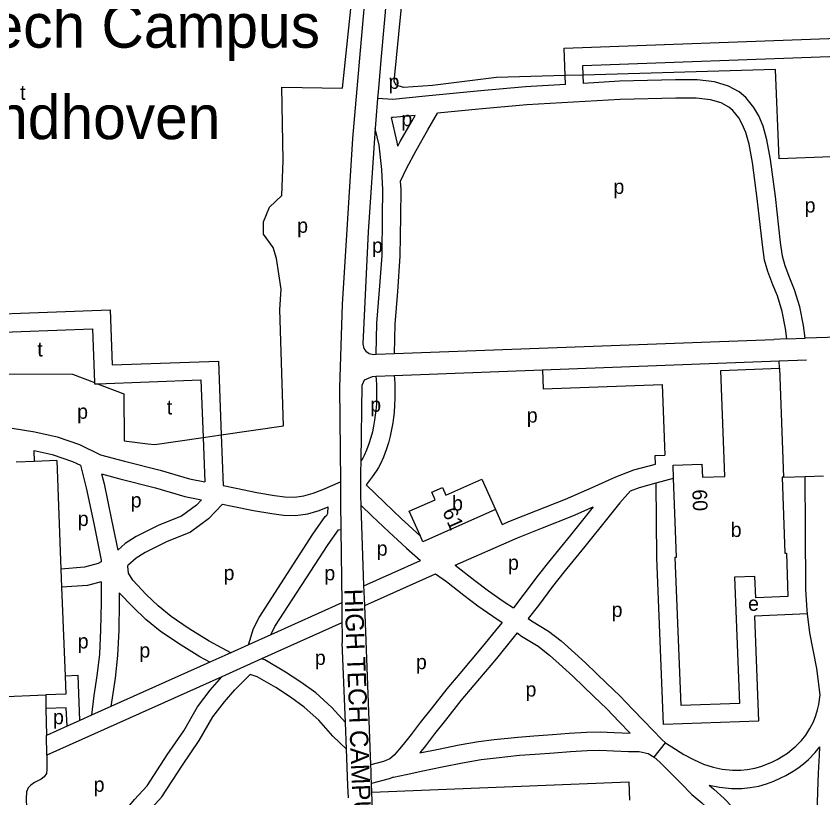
# Model space of a CAD drawing. Extents: x 158358 to 160383, y 379531 to 380764.
# Drawn here: x 159907.3 to 160127.9, y 379892.6 to 380106.3 of the extents above; entities that cross this region are included whole.
import ezdxf

# ---------------------------------------------------------------- set-up
doc = ezdxf.new("R2010")
doc.units = 0
for name, color, linetype in [('BLT_Basislijn', 7, 'Continuous'), ('BLT_Bebouwing', 7, 'Continuous'), ('BLT_Centroide', 7, 'Continuous'), ('BLT_Huisnummer', 7, 'Continuous'), ('BLT_Sport_parknaam', 7, 'Continuous'), ('BLT_Straatnaam', 7, 'Continuous'), ('BLT_Vlakafsluiter', 7, 'Continuous')]:
    doc.layers.add(name, color=color, linetype=linetype)

msp = doc.modelspace()

# ---------------------------------------------------------------- linework, layer by layer
at = {"layer": 'BLT_Basislijn'}
for p, q in [((160117.98, 380018.06), (160122.99, 380018.24)), ((160010.74, 380014.06), (160114.5, 380017.94)), ((160004.98, 380013.84), (160005.73, 380013.87)), ((160005.73, 380013.87), (160010.74, 380014.06)), ((160115.99, 380010.04), (160115.91, 380012.07)), ((160001.63, 379984.81), (160001.95, 380005.4)), ((159912.29, 379984.6), (159912.23, 379987.55)), ((160001.58, 379981.41), (160001.63, 379984.81)), ((160001.56, 379975.23), (160001.58, 379981.41)), ((160082.26, 379978.71), (160087.04, 379979.98)), ((160117.07, 379980.25), (160123.03, 379980.48)), ((160123.03, 379980.48), (160128.03, 379980.66)), ((160001.65, 379972.5), (160001.56, 379975.23)), ((160002.39, 379950.6), (160001.65, 379972.5)), ((160002.44, 379948.93), (160002.39, 379950.6)), ((160002.51, 379947.06), (160002.44, 379948.93)), ((160002.59, 379945.22), (160002.51, 379947.06)), ((160004.28, 379901.62), (160002.59, 379945.22)), ((159996.42, 379937.33), (159996.48, 379934.97)), ((159997.31, 379913.16), (159996.48, 379934.97)), ((159915.37, 379920.71), (159915.45, 379917)), ((159915.45, 379917), (159915.61, 379909.66)), ((159997.59, 379905.87), (159997.31, 379913.16)), ((159997.97, 379895.96), (159997.59, 379905.87)), ((160004.34, 379899.95), (160004.28, 379901.62)), ((160004.41, 379898.31), (160004.34, 379899.95))]:
    msp.add_line(p, q, dxfattribs=at)
for points in [[(160010.67, 380088.45), (160019.2, 380175.38)], [(160009.06, 380172.98), (160004.59, 380131.94), (160003.46, 380120.81), (160001.19, 380094.85)], [(160015.33, 380174.69), (160010.57, 380131.9), (160008.55, 380111.65), (160007.13, 380095.3)], [(159996.53, 380086.65), (160005.42, 380171.89)], [(160057.38, 380090.08), (160057.1, 380097.61), (160131.93, 380100.35)], [(160001.19, 380094.85), (159999.24, 380072.88)], [(160007.13, 380095.3), (160006.38, 380086.62)], [(160062.37, 380090.22), (160062.28, 380092.8), (160132.13, 380095.36), (160133.74, 380051.16), (160150.07, 380051.76), (160152.03, 380006.5), (160139.74, 380005.97), (160141.44, 379966.87), (160146.5, 379967.09), (160147.78, 379937.54)], [(160132.24, 380018.58), (160130.27, 380067.86), (160115.88, 380067.29), (160114.9, 380091.78), (160062.37, 380090.22)], [(160057.38, 380090.08), (160038.61, 380089.52), (160021.17, 380087.36), (160013.18, 380086.85), (160011.16, 380087.43), (160010.67, 380088.45)], [(160057.47, 380087.67), (160057.38, 380090.08)], [(160062.46, 380087.96), (160062.37, 380090.22)], [(160122.99, 380018.24), (160122.6, 380021.73), (160121.55, 380026.84), (160120.14, 380031.51), (160118.8, 380034.73), (160117.57, 380038.02), (160116.83, 380040.67), (160116.3, 380044.41), (160114.9, 380057.04), (160113.58, 380067.14), (160112.59, 380072.49), (160111.54, 380076.22), (160110.32, 380079.08), (160108.99, 380081.34), (160106.83, 380084.06), (160104.95, 380085.6), (160102.04, 380087.22), (160098.2, 380088.38), (160093.49, 380088.95), (160087.56, 380088.88), (160072.28, 380088.52), (160062.46, 380087.96)], [(159963.38, 379991.81), (159980.37, 379994.3), (159979.41, 380026.16), (159979.77, 380031.69), (159978.44, 380040.05), (159977.54, 380043.05), (159974.9, 380046.72), (159974.96, 380050.09), (159976.58, 380054.06), (159979.92, 380057.32), (159980.34, 380066.88), (159979.95, 380086.88), (159996.53, 380086.65)], [(160057.47, 380087.67), (160046.53, 380087.04), (160033.36, 380085.85), (160019.24, 380084.48), (160010.28, 380083.59), (160006.13, 380083.79)], [(160006.38, 380086.62), (160006.13, 380083.79)], [(160006.13, 380083.79), (160005.62, 380077.95), (160005.47, 380075.66)], [(160117.98, 380018.06), (160117.66, 380020.95), (160116.7, 380025.61), (160115.43, 380029.82), (160114.15, 380032.89), (160112.82, 380036.48), (160111.93, 380039.64), (160111.34, 380043.78), (160109.94, 380056.44), (160108.64, 380066.36), (160107.71, 380071.35), (160106.82, 380074.56), (160105.85, 380076.83), (160104.86, 380078.51), (160103.25, 380080.53), (160102.13, 380081.45), (160100.08, 380082.59), (160097.17, 380083.46), (160093.22, 380083.95), (160087.65, 380083.89), (160072.48, 380083.52), (160046.9, 380082.06), (160033.83, 380080.87), (160022.46, 380079.77)], [(160016.37, 380079.17), (160010.41, 380078.58), (160009.91, 380078.6)], [(160011.62, 380070.78), (160011.5, 380071.91), (160009.91, 380078.6)], [(160011.62, 380070.78), (160012.32, 380072.05), (160015.55, 380077.73), (160016.37, 380079.17)], [(160012.43, 380061.24), (160013.99, 380064.71), (160016.68, 380069.61), (160019.89, 380075.26), (160022.46, 380079.77)], [(160005.47, 380075.66), (160003.57, 380047.33), (160002.07, 380016.73)], [(160005.73, 380013.87), (160005.92, 380022.39), (160006.64, 380031.43), (160007.34, 380040.93), (160007.45, 380051.68), (160007.54, 380058.83), (160007.26, 380064.43), (160006.56, 380071.07), (160005.47, 380075.66)], [(159999.24, 380072.88), (159996.47, 380027.49), (159995.68, 380004.78), (159995.96, 379978.96)], [(160010.74, 380014.06), (160010.92, 380022.14), (160011.62, 380031.05), (160012.34, 380040.71), (160012.45, 380051.63), (160012.55, 380058.93), (160012.43, 380061.24)], [(159879.09, 380024.03), (159932.98, 380026), (159933.53, 380010.97), (159962.64, 380012.03), (159963.38, 379991.81)], [(159879.88, 380002.9), (159879.29, 380019.03), (159928.16, 380020.82), (159928.7, 380006.13)], [(160132.24, 380018.58), (160122.99, 380018.24)], [(160002.07, 380016.73), (160002.34, 380015.49), (160002.95, 380014.72), (160003.86, 380014.12), (160004.98, 380013.84)], [(160117.98, 380018.06), (160114.5, 380017.94)], [(159879.88, 380002.9), (159881.44, 380002.96), (159891.59, 380012.61), (159894.85, 380012.61), (159899.8, 380008.51), (159922.73, 380008.4), (159928.7, 380006.13)], [(160051.19, 380009.6), (160115.91, 380012.07)], [(160115.91, 380012.07), (160123.4, 380012.36)], [(160010.67, 380008.06), (160051.19, 380009.6)], [(160051.19, 380009.6), (160051.39, 380004.4), (160083.9, 380005.57), (160084.65, 379986.25)], [(160005.68, 380007.86), (160005.73, 380006.93), (160005.8, 380005.57), (160005.82, 380003.56), (160005.82, 380001.8), (160005.78, 380000.3), (160005.63, 379998.47), (160005.48, 379997.21), (160005.31, 379995.84), (160005.04, 379994.2), (160004.7, 379992.63), (160004.29, 379991.09), (160003.75, 379989.36), (160003.08, 379987.62), (160002.47, 379986.2), (160002.05, 379985.47), (160001.63, 379984.81)], [(160001.95, 380005.4), (160002.53, 380006.92), (160004.71, 380007.83), (160005.68, 380007.86)], [(160010.67, 380008.06), (160010.73, 380007.2), (160010.8, 380005.72), (160010.82, 380003.59), (160010.82, 380001.73), (160010.77, 380000.03), (160010.61, 379997.97), (160010.44, 379996.6), (160010.26, 379995.12), (160009.95, 379993.28), (160009.57, 379991.46), (160009.09, 379989.69), (160008.47, 379987.72), (160007.71, 379985.74), (160006.94, 379983.95), (160006.34, 379982.89), (160005.72, 379981.92), (160004.68, 379980.36), (160002.97, 379978.17)], [(160005.68, 380007.86), (160010.67, 380008.06)], [(159928.7, 380006.13), (159928.71, 380005.79), (159929.51, 380005.82)], [(159929.51, 380005.82), (159957.83, 380006.85), (159958.41, 379991.08)], [(159929.51, 380005.82), (159936.7, 380003.08), (159936.81, 379990.21), (159943.31, 379989.4), (159945.24, 379989.16), (159958.41, 379991.08)], [(159906.22, 379993.66), (159912.43, 379992.63), (159918.5, 379991.29), (159924.63, 379989.17), (159930.38, 379986.42), (159936.95, 379984.61), (159946.69, 379982.2), (159954.66, 379979.82), (159958.85, 379978.99)], [(159963.38, 379991.81), (159963.89, 379977.98)], [(159958.41, 379991.08), (159958.85, 379978.99)], [(159912.23, 379987.55), (159917.14, 379986.47), (159922.73, 379984.54), (159924.87, 379983.52)], [(160082.11, 379983.85), (160082.04, 379986.18), (160084.65, 379986.25)], [(159924.87, 379983.52), (159926.47, 379977.35), (159928.49, 379967.62), (159930.58, 379957.62), (159930.57, 379957.12)], [(160038.34, 379971.39), (160040.14, 379967.32), (160042.42, 379968.33), (160049.4, 379971.04), (160057.54, 379974.28), (160064.83, 379977.47), (160071.26, 379980.35), (160076.21, 379982.25), (160082.11, 379983.85)], [(159930.64, 379981.16), (159935.69, 379979.78), (159945.37, 379977.38), (159953.45, 379974.96), (159957.96, 379974.07)], [(159930.64, 379981.16), (159931.34, 379978.49), (159933.38, 379968.64), (159935.12, 379960.33)], [(159963.89, 379977.98), (159967.42, 379977.24), (159973.11, 379976.05), (159977.9, 379975.27), (159980.77, 379974.89), (159983.42, 379974.8), (159985.99, 379975.13), (159988.48, 379975.88), (159991.15, 379976.94), (159995.96, 379978.96)], [(159995.96, 379978.96), (159996.02, 379973.56)], [(160075.28, 379976.54), (160077.77, 379977.49), (160082.26, 379978.71)], [(160123.68, 379942.88), (160109.16, 379942.28), (160110.25, 379913.58), (160084.32, 379912.62), (160082.49, 379958.17), (160082.26, 379978.71)], [(160123.68, 379942.88), (160123.55, 379943.89), (160123.21, 379949.59), (160123.11, 379966.27), (160123.03, 379980.48)], [(160002.97, 379978.17), (160008.02, 379973.31), (160012.61, 379968.93), (160017.81, 379964.1)], [(160075.28, 379976.54), (160072.35, 379973.26), (160069.09, 379969.12), (160062.79, 379961.3), (160057.08, 379954.3), (160053.99, 379950.42), (160050.12, 379945.21), (160047.33, 379941.64)], [(159957.96, 379974.07), (159956.58, 379972.6), (159952.54, 379969.62), (159946.32, 379967.19), (159940.1, 379964.01), (159937.11, 379962.09), (159935.12, 379960.33)], [(159963.7, 379972.91), (159959.93, 379968.85), (159954.97, 379965.2), (159948.37, 379962.62), (159942.59, 379959.67), (159940.13, 379958.09), (159937.87, 379956.09)], [(159963.7, 379972.91), (159966.4, 379972.35), (159972.2, 379971.13), (159977.16, 379970.33), (159980.35, 379969.9), (159983.66, 379969.79), (159987.04, 379970.23), (159990.13, 379971.16), (159992.62, 379972.14)], [(159992.25, 379969.85), (159992.49, 379970.46), (159992.62, 379972.14)], [(159996.02, 379973.56), (159996.11, 379965.95)], [(160001.65, 379972.5), (160004.56, 379969.7), (160009.18, 379965.29), (160013.99, 379960.82), (160017.83, 379957.44)], [(160027.31, 379956.17), (160044.34, 379963.71), (160051.23, 379966.39), (160059.47, 379969.66), (160065.09, 379972.13)], [(160065.09, 379972.13), (160058.9, 379964.45), (160053.19, 379957.44), (160050.03, 379953.47), (160046.14, 379948.24), (160043.24, 379944.52)], [(159970.79, 379934.42), (159972.22, 379938.9), (159973.71, 379941.92), (159988.45, 379964.69), (159991.8, 379969.48), (159992.25, 379969.85)], [(159976.95, 379937.18), (159978.07, 379939.45), (159992.59, 379961.9), (159995.39, 379965.9), (159996.11, 379965.95)], [(159996.11, 379965.95), (159996.32, 379945.88)], [(159930.57, 379957.12), (159929.74, 379956.66), (159925.99, 379955.64), (159919.55, 379955.16)], [(160002.39, 379950.6), (160017.83, 379957.44)], [(159966, 379932.27), (159960.04, 379935.47), (159954.37, 379939), (159949.65, 379942.19), (159946.09, 379945.09), (159942.86, 379948.2), (159939.16, 379952.08), (159938.03, 379953.99), (159937.84, 379955.92), (159937.87, 379956.09)], [(160027.31, 379956.17), (160032.75, 379952), (160036.49, 379949.16), (160040.49, 379946.36), (160043.24, 379944.52)], [(160002.59, 379945.22), (160022, 379953.82)], [(160022, 379953.82), (160024.92, 379951.71), (160029.71, 379948.02), (160033.55, 379945.11), (160037.67, 379942.24), (160040.15, 379940.56)], [(159930.5, 379951.68), (159926.84, 379950.69), (159919.74, 379950.16)], [(159930.5, 379951.68), (159930.5, 379946), (159930.36, 379938.56), (159930.05, 379931.87), (159929.38, 379925.99), (159928.56, 379920.61), (159927.86, 379915.16)], [(159935.5, 379948.68), (159935.5, 379945.95), (159935.36, 379938.4), (159935.04, 379931.47), (159934.34, 379925.33), (159933.51, 379919.92), (159933.21, 379917.56)], [(159960.24, 379929.69), (159957.54, 379931.14), (159951.64, 379934.8), (159946.67, 379938.18), (159942.77, 379941.35), (159939.32, 379944.68), (159935.5, 379948.68)], [(159996.32, 379945.88), (159976.95, 379937.18)], [(159996.32, 379945.88), (159996.38, 379940.42)], [(160047.33, 379941.64), (160048.24, 379940.99), (160052.83, 379938.15), (160056.31, 379935.48), (160060.07, 379932.13), (160062.94, 379929.48), (160065.95, 379926.57), (160068.73, 379923.9), (160072.33, 379920.45), (160075.8, 379916.85), (160078.94, 379913.6), (160083.87, 379908.56), (160084.87, 379907.66)], [(160127.11, 379920.72), (160126.22, 379927.93), (160124.34, 379937.74), (160123.68, 379942.88)], [(159996.38, 379940.42), (159974.42, 379930.57)], [(159996.38, 379940.42), (159996.42, 379937.33)], [(160040.15, 379940.56), (160039.22, 379939.37), (160034.75, 379933.92), (160028.65, 379926.62), (160025.01, 379922.35), (160020.8, 379916.93), (160017.75, 379913.16), (160015.3, 379909.87), (160013.11, 379907.2), (160010.66, 379904.24), (160009.48, 379903.22), (160007.7, 379902.5), (160004.28, 379901.62)], [(159976.95, 379937.18), (159970.79, 379934.42)], [(160044.25, 379937.69), (160043.13, 379936.25), (160038.6, 379930.73), (160032.47, 379923.4), (160028.89, 379919.19), (160024.72, 379913.82), (160021.7, 379910.1), (160019.24, 379906.79), (160017.71, 379904.92)], [(160044.25, 379937.69), (160045.48, 379936.82), (160049.99, 379934.04), (160053.11, 379931.63), (160056.71, 379928.42), (160059.5, 379925.85), (160062.47, 379922.97), (160065.27, 379920.29), (160068.8, 379916.91), (160072.2, 379913.38), (160075.21, 379910.26)], [(159970.79, 379934.42), (159966, 379932.27)], [(159966, 379932.27), (159960.24, 379929.69)], [(159974.42, 379930.57), (159963.53, 379925.68)], [(159997.31, 379913.16), (159993.61, 379917.31), (159989.22, 379921.28), (159985.13, 379924.23), (159980.93, 379926.99), (159975.29, 379930.29), (159974.42, 379930.57)], [(159960.24, 379929.69), (159933.21, 379917.56)], [(159914.01, 379854.42), (159914.81, 379856.5), (159917.23, 379860.39), (159920.32, 379864.96), (159923.31, 379868.63), (159926.1, 379871.96), (159928.21, 379875.14), (159930.66, 379878.93), (159932.49, 379882.52), (159935.84, 379887.51), (159939.68, 379892.11), (159943.14, 379895.91), (159948.61, 379904.3), (159953.14, 379910.9), (159956.92, 379917.5), (159960.38, 379922), (159963.53, 379925.68)], [(159963.53, 379925.68), (159915.72, 379904.23)], [(159922.57, 379835.62), (159922.15, 379836.47), (159921.03, 379839.73), (159919.26, 379847.46), (159918.59, 379851.38), (159918.61, 379852.46), (159919.3, 379854.26), (159921.42, 379857.67), (159924.33, 379861.97), (159927.16, 379865.44), (159930.12, 379868.96), (159932.39, 379872.41), (159935, 379876.43), (159936.81, 379879.98), (159939.85, 379884.51), (159943.45, 379888.82), (159947.11, 379892.84), (159952.77, 379901.52), (159957.38, 379908.24), (159961.09, 379914.72), (159964.27, 379918.85), (159967.1, 379922.16), (159971.26, 379926.33)], [(159924.72, 379913.75), (159924.24, 379926.05), (159920.66, 379925.88)], [(159997.59, 379905.87), (159993.9, 379909.47), (159990.06, 379913.78), (159986.07, 379917.38), (159982.29, 379920.12), (159978.3, 379922.74), (159973.24, 379925.69), (159971.26, 379926.33)], [(160084.87, 379907.66), (160086.54, 379906.52), (160089.87, 379904.44), (160092.51, 379903.06), (160095.25, 379901.76), (160097.86, 379900.93), (160100.37, 379900.41), (160103.18, 379900.12), (160105.42, 379900.12), (160107.21, 379900.33), (160109.24, 379900.69), (160110.87, 379901.14), (160112.54, 379901.78), (160114.1, 379902.46), (160115.41, 379903.09), (160117.06, 379904.08), (160118.16, 379904.8), (160119.43, 379905.76), (160120.48, 379906.7), (160122.03, 379908.29), (160123.17, 379909.72), (160124.31, 379911.5), (160125.31, 379913.37), (160125.99, 379915.13), (160126.43, 379916.67), (160126.74, 379918.08), (160127.11, 379920.72)], [(159921.2, 379912.17), (159921.01, 379917.21), (159915.45, 379917)], [(159933.21, 379917.56), (159927.86, 379915.16)], [(159927.86, 379915.16), (159924.72, 379913.75)], [(159924.72, 379913.75), (159921.2, 379912.17)], [(159921.2, 379912.17), (159915.61, 379909.66)], [(160017.71, 379904.92), (160022.78, 379905.92), (160028.43, 379907.06), (160033.69, 379907.97), (160037.99, 379908.52), (160044.48, 379909.19), (160048.86, 379909.51), (160053.97, 379909.91), (160058.54, 379910.29), (160063.26, 379910.52), (160066.98, 379910.59), (160070.8, 379910.43), (160075.21, 379910.26)], [(160096.81, 379896.04), (160099.61, 379895.47), (160102.91, 379895.12), (160105.73, 379895.12), (160107.95, 379895.39), (160110.34, 379895.81), (160112.43, 379896.39), (160114.44, 379897.15), (160116.18, 379897.92), (160117.78, 379898.68), (160119.71, 379899.85), (160121.04, 379900.71), (160122.61, 379901.9), (160123.94, 379903.09), (160125.78, 379904.98), (160127.04, 379906.56)], [(160127.17, 379866.21), (160126.99, 379868.21), (160126.87, 379870.76), (160126.67, 379873.46), (160126.56, 379876.53), (160126.42, 379879.63), (160126.4, 379882.85), (160126.31, 379888.02), (160126.49, 379894.33), (160126.67, 379899.36), (160126.94, 379904.28), (160127.04, 379906.56)], [(159915.72, 379904.23), (159915.72, 379900.36), (159915.58, 379899.27), (159914.98, 379898.31), (159914.11, 379897.68), (159912.3, 379896.77), (159911.3, 379896.08), (159910.61, 379895.34), (159910.14, 379894.25), (159910.03, 379892.31), (159911.48, 379854.38)], [(160010.49, 379898.24), (160013.92, 379898.95), (160018.48, 379899.98), (160023.76, 379901.02), (160029.35, 379902.15), (160034.43, 379903.03), (160038.56, 379903.55), (160044.92, 379904.21), (160049.23, 379904.52), (160054.38, 379904.92), (160058.87, 379905.3), (160063.42, 379905.52), (160066.92, 379905.58), (160070.6, 379905.43), (160074.71, 379905.27), (160077.61, 379905.23), (160080.11, 379904.72), (160081.74, 379903.74)], [(160081.74, 379903.74), (160083.29, 379902.35), (160085.96, 379899.66), (160088.91, 379896.67), (160092.06, 379893.52), (160094.76, 379891.23), (160097.37, 379888.83), (160098.77, 379887.41)], [(160004.48, 379896.51), (160004.41, 379898.31)], [(160010.49, 379898.24), (160009.27, 379897.75), (160004.48, 379896.51)], [(160004.57, 379894.09), (160074.83, 379896.98), (160075.04, 379891.94)], [(159998.14, 379892.58), (159997.97, 379895.96)], [(160004.57, 379894.09), (160004.48, 379896.51)], [(160096.81, 379896.04), (160098.06, 379894.98), (160100.85, 379892.43), (160103.09, 379890.14), (160106.17, 379887.26), (160109.28, 379884.48), (160112.65, 379881.25), (160115.42, 379878.23), (160118.11, 379875.16), (160121.5, 379871.7), (160124.95, 379868.32), (160127.17, 379866.21)], [(160004.76, 379889.27), (160004.57, 379894.09)]]:
    msp.add_lwpolyline(points, dxfattribs=at)
at = {"layer": 'BLT_Bebouwing'}
msp.add_line((159902.29, 379920.2), (159915.37, 379920.71), dxfattribs=at)
for points in [[(160087.04, 379979.98), (160086.9, 379983.54), (160094.8, 379983.85), (160094.93, 379980.29), (160101.11, 379980.49), (160099.97, 380009.4), (160115.99, 380010.04)], [(160115.99, 380010.04), (160117.07, 379980.25)], [(159912.29, 379984.6), (159907.29, 379984.4)], [(159918.42, 379984.84), (159912.29, 379984.6)], [(159918.42, 379984.84), (159919.55, 379955.16)], [(160014.75, 379970.97), (160021.83, 379974.09), (160020.91, 379976.18), (160023.85, 379977.47), (160024.77, 379975.38), (160034.65, 379979.74), (160038.34, 379971.39)], [(160087.49, 379958.37), (160087.86, 379958.38), (160087.04, 379979.98)], [(160117.07, 379980.25), (160116.73, 379980.24), (160117.51, 379959.53), (160117.92, 379959.5), (160118.31, 379947.66)], [(160017.81, 379964.1), (160014.75, 379970.97)], [(160038.34, 379971.39), (160018.49, 379962.56), (160017.81, 379964.1)], [(160118.31, 379947.66), (160109.54, 379947.3), (160109.28, 379953.1), (160103.75, 379952.9), (160105.07, 379918.39), (160089.12, 379917.8), (160087.49, 379958.37)], [(159919.55, 379955.16), (159919.74, 379950.16)], [(159919.74, 379950.16), (159920.66, 379925.88)], [(159920.66, 379925.88), (159920.85, 379920.92), (159915.37, 379920.71)]]:
    msp.add_lwpolyline(points, dxfattribs=at)
at = {"layer": 'BLT_Vlakafsluiter'}
for p, q in [((160062.37, 380090.22), (160057.38, 380090.08)), ((159958.41, 379991.08), (159963.38, 379991.81)), ((159915.72, 379904.23), (159915.61, 379909.66)), ((160081.74, 379903.74), (160084.87, 379907.66))]:
    msp.add_line(p, q, dxfattribs=at)

# ---------------------------------------------------------------- texts
at = {"layer": 'BLT_Centroide'}
for s, p in [('p', (160009.11, 380086.44)), ('t', (159908.39, 380083.46)), ('p', (160012.64, 380076.26)), ('p', (160070.61, 380057.72)), ('p', (160122.89, 380052.63)), ('p', (159984.13, 380047.1)), ('p', (160004.56, 380041.64)), ('t', (159913.08, 380013.29)), ('t', (159948.5, 379997.42)), ('p', (160004.11, 379998.14)), ('p', (159923.97, 379996.24)), ('p', (160046.92, 379995.2)), ('p', (159938.61, 379972)), ('b', (160026.48, 379971.16)), ('p', (159924.15, 379966.92)), ('b', (160102.67, 379963.91)), ('p', (160005.89, 379958.8)), ('p', (160041.78, 379954.92)), ('p', (159964.01, 379952.11)), ('p', (159991.56, 379952.06)), ('e', (160107.42, 379943.73)), ('p', (160070.11, 379942.04)), ('p', (159924.13, 379933.43)), ('p', (159940.98, 379930.94)), ('p', (159988.97, 379928.93)), ('p', (160016.6, 379927.76)), ('p', (160046.57, 379920.27)), ('p', (159917.37, 379912.71)), ('p', (159928.49, 379894.24))]:
    msp.add_text(s, height=4, dxfattribs=at).set_placement(p)
at = {"layer": 'BLT_Huisnummer'}
for s, rotation, p in [('60', 272.3558, (160092.15, 379976.86)), ('61', 293.9859, (160023.75, 379970.87))]:
    msp.add_text(s, height=4, rotation=rotation, dxfattribs=at).set_placement(p)
at = {"layer": 'BLT_Sport_parknaam'}
for s, p in [('High Tech Campus', (159853.03, 380097.7)), ('Eindhoven', (159887.29, 380072.7))]:
    msp.add_text(s, height=12, dxfattribs=at).set_placement(p)
at = {"layer": 'BLT_Straatnaam'}
msp.add_text('HIGH TECH CAMPUS', height=5, rotation=272.1866, dxfattribs=at).set_placement((159997.02, 379949.64))

doc.saveas('drawing.dxf')
